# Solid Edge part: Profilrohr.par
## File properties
Dokumentum tartalom típus: 0
Last saved by: bmolnar
Revision: 76
Sűrűség: 0,000 kg/m^3
Pontosság: 0,990
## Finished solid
Body 1: solid body, 59 faces, 170 edges, 112 vertices.
  Faces by surface: plane 30, cylinder 29
  Edges by curve: line 112, circle 58
Bounding box of the edges (mm): 40.000 x 19.000 x 40.000, from (-20, -9.5, -20) to (20, 9.5, 20).
Cylindrical faces by radius (mm): R0.2 x12, R0.5 x12, R5 x4, R12.5 x1
Planar faces by outward normal: +x 7, +y 1, +z 7, -x 7, -y 1, -z 7
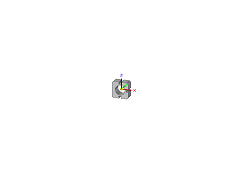
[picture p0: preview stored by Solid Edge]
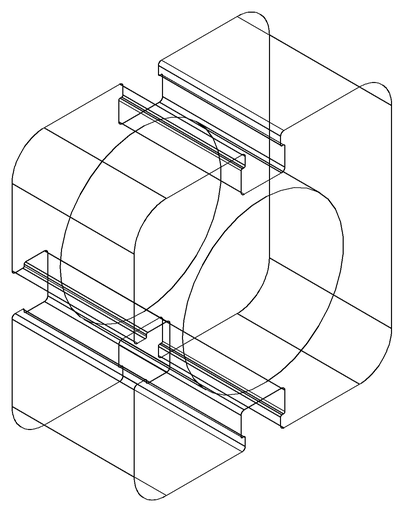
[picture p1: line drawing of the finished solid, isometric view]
